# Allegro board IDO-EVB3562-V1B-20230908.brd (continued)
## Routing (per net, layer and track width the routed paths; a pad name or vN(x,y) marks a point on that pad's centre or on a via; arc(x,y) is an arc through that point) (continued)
RMII_MDIO: length 16.3
  TOP w0.127: v1(78.05,47.76) 78.05,49.22 78.75,49.92 78.75,55.51 80.68,57.44 80.68,58.07 81.79,59.19 M1.41
  BOTTOM w0.127: v1(78.05,47.76) 79.34,49.05 R202.1
RMII_RST_: length 4.4
  BOTTOM w0.127: U17.21 33.82,54.64 34.2,54.26 C340.2 R204.1 R208.2
RMII_RSTN: length 57.5
  TOP w0.127: M1.32 80.52,50.19 79.03,48.7 79.03,46.63 79.15,46.52 79.15,46.13 78.9,45.88 77.31,45.88 v1(76.28,46.91)
  BOTTOM w0.127: v1(76.28,46.91) 75.77,46.39 66.32,46.39 61.29,41.36 50.09,41.36 43.97,47.48 38.65,47.48 36.44,49.69 36.44,51.57 R208.1
RMII_RXD0: length 59.9
  TOP w0.127: M1.37 81.53,55.19 81.07,55.64 v1(80.57,55.64)
  BOTTOM w0.127: R197.2 43.49,59.13 43.49,50.68 50.96,43.21 60.42,43.21 65.68,48.47 74.57,48.47 75.81,49.71 76.47,49.71 76.78,50.02 76.78,51.39 77.54,52.16 77.54,54.18 79.1,55.73 80.48,55.73 v1(80.57,55.64)
RMII_RXD1: length 64.4
  TOP w0.127: v1(83.22,55.63) 83.06,55.48 83.06,52.71 82.54,52.19 M1.34
  BOTTOM w0.127: R196.2 42.04,59.6 43.24,58.4 43.24,50.57 50.85,42.96 60.53,42.96 65.78,48.21 74.67,48.21 75.92,49.46 76.58,49.46 77.03,49.91 77.03,51.28 77.8,52.05 77.8,54.07 79.2,55.47 80.07,55.47 80.37,55.18 80.76,55.18 81.22,55.63 v1(83.22,55.63)
RMII_RXER: length 67.9
  TOP w0.127: M1.33 81.16,51.19 78.78,48.81 78.78,46.62 v1(78.55,46.39)
  BOTTOM w0.127: v1(78.55,46.39) 78.07,45.91 77.22,45.91 76.61,45.3 66.82,45.3 61.76,40.24 49.62,40.24 43.47,46.39 38.2,46.39 36.04,48.55 33.18,48.55 29.75,51.98 28.99,51.98 27.97,52.99 27.97,54.84 R210.1
RMII_TXD0: length 6.1
  TOP w0.127: M1.40 81.91,58.19 79.64,55.91 v1(79.64,54.35)
  BOTTOM w0.127: R199.1 v1(79.64,54.35)
RMII_TXD0_: length 57.7
  BOTTOM w0.127: U17.16 37.88,54.15 37.88,49.36 38.99,48.24 44.28,48.24 50.41,42.12 60.98,42.12 66.05,47.2 75.09,47.2 76.34,48.44 77,48.44 78.05,49.49 78.05,50.86 78.65,51.46 78.65,52.81 R199.2
RMII_TXD1: length 6.6
  TOP w0.127: v1(81.06,53.37) 80.1,54.33 80.1,55.95 81.34,57.19 M1.39
  BOTTOM w0.127: R198.1 80.37,52.67 v1(81.06,53.37)
RMII_TXD1_: length 57
  BOTTOM w0.127: U17.17 35.82,54.48 37.26,53.05 37.26,49.59 38.86,47.99 44.18,47.99 50.3,41.86 61.08,41.86 66.16,46.94 75.2,46.94 76.44,48.19 77.1,48.19 78.3,49.39 78.3,50.76 78.9,51.36 78.9,52.05 R198.2
RMII_TXEN: length 8.3
  TOP w0.127: M1.38 83.32,56.19 83.68,55.83 83.68,55.18 v1(83.53,55.02)
  BOTTOM w0.127: R201.1 80.49,51.59 80.83,51.93 80.83,52.77 80.97,52.91 81.26,52.91 81.7,53.35 81.7,54.63 82,54.92 83.43,54.92 v1(83.53,55.02)
RMII_TXEN_: length 58
  BOTTOM w0.127: R201.2 79.47,51.57 78.55,50.65 78.55,49.28 77.21,47.94 76.55,47.94 75.3,46.69 66.26,46.69 61.19,41.61 50.2,41.61 44.07,47.74 38.75,47.74 36.69,49.79 36.69,53.08 36.56,53.22 35.19,53.22 34.48,53.93 34.48,54.49 34.32,54.65 U17.20
RN: length 2.3
  BOTTOM w0.102: R206.1 34.72,61.74 34.72,60.76 34.7,60.73 34.7,60.24 34.82,60.12 U17.6
RP: length 2.3
  BOTTOM w0.102: R206.2 34.47,61.74 34.47,60.86 34.44,60.84 34.44,60.22 34.32,60.1 U17.5
RS232_RX6: length 1.5
  TOP w0.127: U42.13 110.55,13.67 110.62,13.75 L42.1
RS232_RX6_: length 51.6
  TOP w0.127: v1(96.48,4.68) 96.1,4.3 93.66,4.3 J55.2 ; L42.2 112.89,13.75 113.01,13.62 117.89,13.62 120.86,10.65 123.93,10.65 v1(124.24,10.95)
  BOTTOM w0.127: v1(124.24,10.95) 125.02,10.17 125.02,8.8 122.52,6.3 120.49,6.3 120.28,6.51 118.55,6.51 118.06,6.03 99.34,6.03 98.39,5.08 96.88,5.08 v1(96.48,4.68)
RS232_RX8: length 3.7
  TOP w0.127: U42.8 102.91,11.07 102.31,11.67 101.48,11.67 101.14,11.34 L41.1
RS232_RX8_: length 25.3
  TOP w0.127: L41.2 98.96,11.34 98.2,10.57 95.2,10.57 91.46,6.83 91.46,2.04 90.77,1.35 83.51,1.35 J54.2
RS232_TX6: length 1.6
  TOP w0.127: L43.1 110.73,14.64 110.41,14.32 U42.14
RS232_TX6_: length 51.1
  TOP w0.127: v1(125,10.95) 124.54,11.42 123.92,11.42 123.4,10.9 120.99,10.9 118.02,13.88 113.19,13.88 112.43,14.64 L43.2 ; J55.3 95.32,3.97 96.66,3.97 v1(97.31,4.61)
  BOTTOM w0.127: v1(97.31,4.61) 98.29,4.61 99.45,5.77 118.17,5.77 118.65,6.26 120.17,6.26 120.38,6.04 122.63,6.04 125.38,8.8 125.38,10.57 v1(125,10.95)
RS232_TX8: length 1.8
  TOP w0.127: U42.7 103.03,11.72 102.58,12.17 L40.1
RS232_TX8_: length 25.1
  TOP w0.127: L40.2 101.04,11.89 99.15,11.89 98.09,10.83 95.1,10.83 91.21,6.94 91.21,2.14 90.66,1.6 85.26,1.6 J54.3
RSET0: length 4.8
  BOTTOM w0.203: U16.39 51.67,58.71 51.39,58.99 51.39,59.35 50.69,60.05 50.69,61.2 49.75,62.14 R183.2
RSET2: length 3
  BOTTOM w0.127: U15.31 71.4,59.45 70.98,59.88 70.72,59.88 69.86,60.74 R158.2
RXD0: length 5.2
  BOTTOM w0.127: U17.9 37.1,59.06 38.19,60.15 39.73,60.15 40.22,60.64 40.88,60.64 R197.1
RXD1: length 6.6
  BOTTOM w0.127: U17.10 37.66,58.56 R212.1 39.26,59.04 40.43,59.04 R196.1 R211.1
RXDV: length 3.3
  BOTTOM w0.127: R217.1 38.13,60.74 37.52,60.13 36.02,60.13 35.82,59.92 U17.8
RXER/FXEN: length 3.5
  BOTTOM w0.127: R210.2 R220.1 30.77,56.42 31.4,57.06 U17.28
RXN: length 25.2
  BOTTOM w0.102: R206.8 34.72,63.04 34.72,63.37 34.81,63.45 34.81,64.13 D80.4 34.81,64.56 34.81,65.69 35.52,66.4 35.52,67.62 33.05,70.09 33.05,71.65 28.82,75.88 25.26,75.88 24.57,75.19 24.57,74 22.61,72.04 J23.6
RXP: length 25.2
  BOTTOM w0.102: J23.3 26.12,74.53 26.12,73.79 25.31,72.98 24.59,72.98 24.42,73.16 24.42,73.49 24.82,73.89 24.82,75.09 25.36,75.62 28.72,75.62 32.8,71.54 32.8,69.98 35.26,67.52 35.26,67.29 D80.3 35.26,66.8 35.26,66.51 34.55,65.8 34.55,63.56 34.47,63.47 34.47,63.04 R206.7
SARADC0_BOOT: length 24.1
  TOP w0.127: v1(87.63,61.03) R1202.1 ; v1(79.92,43.97) 79.53,44.36 M1.179
  BOTTOM w0.127: v1(79.92,43.97) 79.92,44.36 82.71,47.15 82.71,49.72 86.14,53.14 86.14,57.06 86.65,57.56 87.41,57.56 88.88,59.04 88.88,59.77 v1(87.63,61.03)
SARADC0_IN1_KEY/RECOVERY: length 26.2
  TOP w0.203: M1.56 68.87,62.89 68.1,63.66 68.1,65.69 70.77,68.35 73.9,68.35 76.41,70.86 76.41,74.57 74.55,76.43 74.55,81.34 R264.1
SARADC1_IN0: length 99.2
  TOP w0.127: v1(64.02,66.71) 64.02,66.76 63.91,66.86 C272.2 63.51,66.87 63.51,63.61 62.87,62.97 M1.62 ; v1(74.04,25.35) 73.41,25.98 73.41,31.89 71.66,33.64 71.66,37.05 72.85,38.24 72.85,50.69 71.85,51.69 71.85,53.33 71.15,54.03 71.15,55.05 68.38,57.82 68.38,60.64 67.6,61.42 v1(66.43,61.42) ; v1(112.17,9.68) 112.17,9.18 111.92,8.92 R350.1
  BOTTOM w0.127: v1(74.04,25.35) 74.32,25.07 78.21,25.07 84.61,18.67 85.66,18.67 90.35,13.98 101.34,13.98 102.1,13.22 107.74,13.22 110.39,10.57 111.44,10.57 112.15,9.86 112.15,9.7 v1(112.17,9.68) ; v1(64.02,66.71) 64.09,66.63 64.14,66.63 64.19,66.58 64.38,66.58 65.9,65.07 66.5,64.46 66.5,61.48 v1(66.43,61.42)
SARADC1_IN1: length 102.9
  TOP w0.127: v1(73.26,25.38) 73.05,25.59 73.05,31.78 71.38,33.46 71.38,37.17 72.52,38.31 72.52,48.99 69.76,51.75 69.76,53.35 v1(68.98,54.13) ; v1(62.9,66.58) C273.2 62.47,66.85 62.47,63.54 61.87,62.94 M1.63 ; v1(111.45,9.68) 111.45,9.03 R349.1
  BOTTOM w0.127: v1(62.9,66.58) 63.49,65.99 64.25,65.99 66.12,64.13 66.12,62.09 65.84,61.81 65.84,60.32 64.49,58.97 64.49,54.6 65.28,53.81 68.66,53.81 v1(68.98,54.13) ; v1(73.26,25.38) 73.26,25.3 73.86,24.69 78.19,24.69 84.5,18.39 85.4,18.39 90.19,13.6 101.18,13.6 101.94,12.84 107.58,12.84 110.23,10.19 110.97,10.19 111.45,9.71 v1(111.45,9.68)
SARADC1_IN2: length 94.5
  TOP w0.127: v1(61.88,66.58) C274.2 61.46,66.85 61.46,63.52 60.87,62.93 M1.64 ; R348.1 v1(102.78,8.45) ; v1(71.66,23.03) 71.66,23.04 72.42,23.8 72.42,31.48 70.82,33.08 70.82,37.4 71.86,38.44 71.86,48.28 68.05,52.09 68.05,53.14 65.23,55.95 65.23,59.04 v1(63.84,60.43)
  BOTTOM w0.127: v1(61.88,66.58) 64.47,64 64.47,60.96 63.94,60.43 v1(63.84,60.43) ; v1(71.66,23.03) 71.66,23.04 71.71,23.09 72.36,23.09 72.55,22.89 76.11,22.89 77.1,21.9 78.44,21.9 84.05,16.3 84.18,16.3 86.68,13.79 86.68,12.3 88.14,10.84 90.08,10.84 90.36,11.12 97.24,11.12 98,10.35 100.69,10.35 102.6,8.45 v1(102.78,8.45)
SARADC1_IN3: length 94.5
  TOP w0.127: v1(63.8,61.13) 64.13,61.13 65.26,60 66.73,60 67.29,59.44 67.29,56.34 68.38,55.25 68.38,53.96 69.35,52.99 69.35,51.51 72.19,48.67 72.19,38.37 71.1,37.28 71.1,33.27 72.7,31.66 72.7,23.09 v1(72.11,22.49) ; v1(60.87,66.58) C275.2 60.44,66.85 60.44,66.03 60.36,65.95 60.36,64.1 59.87,63.6 M1.65 ; R347.1 v1(101.76,8.45)
  BOTTOM w0.127: v1(101.76,8.45) 101.76,8.57 100.36,9.97 97.84,9.97 97.03,10.78 90.57,10.78 90.23,10.45 88.02,10.45 86.3,12.17 86.3,13.77 86.2,13.87 86.2,13.88 84.06,16.02 83.93,16.02 78.32,21.62 76.98,21.62 76.09,22.51 72.13,22.51 v1(72.11,22.49) ; v1(63.8,61.13) 63.8,63.65 v1(60.87,66.58)
SARADC1_IN4: length 94.7
  TOP w0.127: R346.1 101.03,8.08 v1(101.03,8.45) ; v1(71.44,22.27) 71.12,22.59 71.12,23.26 72.14,24.28 72.14,31.29 70.54,32.89 70.54,37.51 70.54,37.52 70.54,37.52 71.53,38.51 71.53,48.15 67.72,51.96 67.72,53 64.9,55.81 64.9,58.53 63.2,60.23 63.2,60.73 v1(63.05,60.89) ; v1(59.98,66.6) 59.85,66.72 C276.2 59.47,66.89 59.47,66.2 59.95,65.72 59.95,64.32 58.87,63.24 M1.66
  BOTTOM w0.127: v1(59.98,66.6) 63.17,63.4 63.17,61.02 v1(63.05,60.89) ; v1(71.44,22.27) 71.74,21.98 76,21.98 76.23,21.98 76.87,21.34 78.21,21.34 83.81,15.74 83.94,15.74 85.92,13.76 85.92,11.99 87.82,10.09 90.46,10.09 90.82,10.45 96.82,10.45 97.81,9.47 100.15,9.47 101.03,8.59 v1(101.03,8.45)
SARADC1_IN5: length 96
  TOP w0.127: v1(100.32,8.45) 100.32,8.39 R345.1 ; v1(59,66.58) 58.83,66.75 C277.2 58.45,66.89 58.45,66.45 59.57,65.34 59.57,64.52 57.87,62.82 M1.67 ; v1(70.79,22.01) 70.79,23.4 71.86,24.47 71.86,31.1 70.41,32.56 70.26,32.71 70.26,37.72 71.2,38.66 71.2,48.01 67.39,51.82 67.39,52.86 64.57,55.68 64.57,58.38 62.65,60.3 v1(62.55,60.3)
  BOTTOM w0.127: v1(70.79,22.01) 71.1,21.7 76.11,21.7 76.59,21.23 76.75,21.06 78.09,21.06 83.7,15.46 83.76,15.46 83.81,15.4 85.41,13.8 85.41,11.86 87.59,9.68 90.66,9.68 91.1,10.12 96.61,10.12 97.78,8.96 99.94,8.96 100.32,8.57 v1(100.32,8.45) ; v1(59,66.58) 59.71,65.87 60.05,65.87 62.58,63.34 62.58,61.67 62.45,61.54 62.45,60.39 v1(62.55,60.3)
SD_CD: length 2.8
  TOP w0.127: R28.2 112.68,74.12 112.72,74.16 J6.9
SD_CLK: length 38.2
  TOP w0.127: v1(81.28,69.93) 81.02,69.93 80.82,69.72 79.86,69.72 78.65,68.51 C279.2 R25.2 ; J6.5 v1(108.32,77.38)
  BOTTOM w0.127: v1(81.28,69.93) 81.45,69.93 81.93,70.41 81.93,70.59 81.71,70.81 81.71,70.99 81.89,71.17 82.07,71.17 82.29,70.95 82.47,70.95 82.65,71.13 82.65,71.31 82.39,71.57 82.39,71.75 82.57,71.93 82.75,71.93 83.01,71.67 83.19,71.67 83.54,72.01 94.52,72.01 98.39,75.88 105.47,75.88 106.97,77.38 v1(108.32,77.38)
SDMMC0_CLK: length 7.3
  TOP w0.127: M1.51 73.87,63.33 75.22,64.68 76.61,64.68 77.63,65.69 R25.1
SDMMC0_CMD: length 47.5
  TOP w0.127: v1(80.41,70.31) 79.79,70.31 78.34,68.87 76.56,68.87 74.87,67.17 71.26,67.17 70.23,66.15 70.23,65.24 71.9,63.56 72.58,63.56 72.87,63.26 M1.52 ; J6.3 v1(106.12,77.38)
  BOTTOM w0.127: v1(106.12,77.38) 105,76.26 98.23,76.26 94.49,72.52 82.61,72.52 v1(80.41,70.31)
SDMMC0_D0: length 47.1
  TOP w0.127: v1(80.28,68.45) 79.62,68.45 79.43,68.26 79.43,67.77 79.76,67.44 79.76,66.6 79.18,66.02 79.01,66.02 78.65,66.38 78.47,66.38 78.29,66.2 78.29,66.02 78.65,65.66 78.65,65.48 78.48,65.31 77.97,65.31 76.82,64.17 75.6,64.17 74.87,63.44 M1.50 ; J6.7 v1(110.52,77.38)
  BOTTOM w0.127: v1(80.28,68.45) 80.64,68.8 81.31,68.8 81.85,69.35 81.85,69.79 83.57,71.5 94.55,71.5 98.42,75.37 105.68,75.37 107.06,76.75 109.89,76.75 v1(110.52,77.38)
SDMMC0_D1: length 47.8
  TOP w0.127: M1.49 75.87,63.42 76.36,63.91 76.93,63.91 78.07,65.06 78.7,65.06 78.98,65.34 79.25,65.34 79.65,64.94 79.85,64.94 80.03,65.12 80.03,65.28 79.56,65.74 79.56,65.92 79.74,66.1 79.92,66.1 80.31,65.71 80.52,65.71 80.7,65.89 80.7,66.04 80.28,66.46 80.28,66.64 v1(80.28,67.74) ; J6.8 111.62,76.95 v1(111.2,77.38)
  BOTTOM w0.127: v1(80.28,67.74) 80.28,67.79 80.92,68.43 81.29,68.43 82.1,69.24 82.1,69.68 83.67,71.25 94.66,71.25 98.52,75.11 105.78,75.11 107.16,76.49 110.31,76.49 v1(111.2,77.38)
SDMMC0_D2: length 47
  TOP w0.127: M1.54 70.87,63.87 69.72,65.03 69.72,66.36 71.04,67.68 74.4,67.68 76.33,69.62 77.9,69.62 79.41,71.13 v1(79.41,71.25) ; J6.1 v1(103.92,77.38)
  BOTTOM w0.127: v1(103.92,77.38) 103.45,77.85 103.28,77.85 103.16,77.72 103.16,77.02 103.03,76.89 102.78,76.89 102.65,77.02 102.65,77.72 102.52,77.85 101.01,77.85 99.93,76.76 97.98,76.76 94.24,73.03 82.32,73.03 80.55,71.25 v1(79.41,71.25)
SDMMC0_D3: length 48.5
  TOP w0.127: M1.53 71.87,63.23 69.97,65.13 69.97,66.25 71.15,67.43 74.5,67.43 76.4,69.32 78.44,69.32 v1(79.89,70.78) ; J6.2 v1(105.02,77.38)
  BOTTOM w0.127: v1(105.02,77.38) 104.15,76.51 102.35,76.51 102.23,76.64 102.23,77.22 102.1,77.35 101.85,77.35 101.72,77.22 101.72,76.64 101.59,76.51 101.34,76.51 101.21,76.64 101.21,77.07 101.08,77.2 100.83,77.2 100.7,77.07 100.7,76.64 100.58,76.51 98.1,76.51 94.37,72.77 82.43,72.77 80.43,70.78 v1(79.89,70.78)
SDMMC0_DET_L: length 88.6
  TOP w0.127: M1.171 79.87,18.56 79.27,19.16 77.53,19.16 77.16,19.52 76.88,19.52 76.81,19.59 76.11,19.59 75.09,20.61 75.09,21.75 76.89,23.55 79.43,23.55 79.92,24.04 79.92,25.69 80.98,26.75 80.98,32.98 81.21,33.21 81.21,49.03 v1(81.06,49.18) ; v1(87.82,58.81) 87.64,58.99 87.64,59.62 89.39,61.37 93.25,61.37 93.76,61.88 94.9,61.88 96.04,63.02 111.13,63.02 112.17,64.07 112.17,69.88 112.68,70.39 R28.1 R431.2
  BOTTOM w0.127: v1(87.82,58.81) 86.57,58.81 85.38,57.61 85.38,53.75 83.98,52.36 83.57,52.36 81.06,49.84 v1(81.06,49.18)
SDMMC1_CLK: length 84.4
  TOP w0.127: v1(74.45,35.95) 74.45,36.98 74.88,37.4 74.88,48.75 77.54,51.42 77.54,52.82 77.38,52.99 77.38,59.56 78.41,60.59 79.1,60.59 79.37,60.87 81.19,60.87 81.51,61.19 M1.43 ; R227.1 v1(119.58,31.98)
  BOTTOM w0.127: v1(119.58,31.98) 117.98,31.98 116.63,30.62 114.85,30.62 111.6,27.37 109.84,27.37 107.05,24.58 95.1,24.58 94.63,25.05 94.03,25.05 85.46,33.62 84.91,33.62 83.61,34.92 82.12,36.41 75.63,36.41 75.16,35.93 74.47,35.93 v1(74.45,35.95)
SDMMC1_CMD: length 87.3
  TOP w0.127: U18.16 v1(118.79,30.13) ; v1(74.12,34.64) 73.86,34.89 73.86,36.92 74.5,37.56 74.5,49.09 76.61,51.21 76.61,59.52 78.2,61.1 78.89,61.1 79.16,61.37 80.53,61.37 80.87,61.72 M1.44
  BOTTOM w0.127: v1(118.79,30.13) 118.45,29.79 118.45,29.61 118.81,29.25 118.81,29.07 118.63,28.89 118.45,28.89 118.09,29.25 117.91,29.25 117.73,29.07 117.73,28.89 118.14,28.48 118.14,28.3 117.96,28.12 116.78,28.12 116.7,28.05 113.71,28.05 109.23,23.56 93.99,23.56 84.94,32.61 84.67,32.61 82.75,34.52 74.23,34.52 v1(74.12,34.64)
SDMMC1_D0: length 86.5
  TOP w0.127: v1(72.76,35.39) 72.29,35.86 72.29,36.79 73.48,37.98 73.48,49.51 75.6,51.63 75.6,59.94 76.87,61.21 M1.48 ; U18.18 v1(116.99,30.03)
  BOTTOM w0.127: v1(72.76,35.39) 73.04,35.1 74.4,35.1 74.73,34.78 82.86,34.78 84.77,32.86 85.09,32.86 94.14,23.82 109.12,23.82 113.61,28.3 116.6,28.3 116.73,28.43 116.73,28.68 116.6,28.81 114.62,28.81 114.49,28.94 114.49,29.19 114.62,29.32 116.28,29.32 v1(116.99,30.03)
SDMMC1_D1: length 87.5
  TOP w0.127: U18.19 v1(116.09,30.03) ; M1.47 77.87,61.85 75.85,59.83 75.85,51.52 73.74,49.41 73.74,37.87 72.91,37.05 72.91,36.29 v1(72.76,36.14)
  BOTTOM w0.127: v1(116.09,30.03) 115.7,29.64 114.59,29.64 111.16,26.22 110.98,26.22 110.46,26.74 110.28,26.74 110.1,26.56 110.1,26.38 110.62,25.86 110.62,25.68 110.44,25.5 110.26,25.5 109.67,26.09 109.48,26.09 109.31,25.92 109.31,25.74 109.91,25.14 109.91,24.96 109.73,24.78 109.55,24.78 108.9,25.43 108.72,25.43 108.54,25.25 108.54,25.07 109.19,24.42 109.19,24.24 109.02,24.07 94.29,24.07 85.25,33.12 84.88,33.12 82.96,35.03 82.67,35.03 82.54,35.16 82.54,35.45 82.41,35.58 82.16,35.58 82.03,35.45 82.03,35.16 81.9,35.03 75.91,35.03 75.79,35.16 75.79,35.47 75.66,35.59 75.4,35.59 75.28,35.47 75.28,35.16 75.15,35.03 74.83,35.03 74.51,35.36 73.54,35.36 v1(72.76,36.14)
SDMMC1_D2: length 87.7
  TOP w0.127: v1(72.83,34.21) 73.01,34.38 73.01,34.99 73.22,35.2 73.22,37 73.99,37.77 73.99,49.3 76.11,51.42 76.11,59.73 77.99,61.61 78.68,61.61 78.87,61.8 M1.46 ; v1(120.4,30.11) 120.59,29.92 U18.14
  BOTTOM w0.127: v1(120.4,30.11) 120.4,29.54 118.41,27.54 113.92,27.54 109.44,23.06 93.78,23.06 84.73,32.1 84.46,32.1 82.64,33.92 73.12,33.92 v1(72.83,34.21)
SDMMC1_D3: length 86.7
  TOP w0.127: U18.15 v1(119.69,30.13) ; v1(73.48,34.42) 73.48,36.89 74.24,37.66 74.24,49.2 76.36,51.31 76.36,59.62 78.09,61.35 78.78,61.35 79.06,61.63 79.66,61.63 79.87,61.84 M1.45
  BOTTOM w0.127: v1(119.69,30.13) 119.69,29.18 118.3,27.79 113.82,27.79 109.33,23.31 93.88,23.31 84.84,32.35 84.56,32.35 82.74,34.17 73.72,34.17 v1(73.48,34.42)
SENSER_SCL: length 1.3
  TOP w0.127: R343.2 67.46,10.38 U20.6
SENSER_SDA: length 1.2
  TOP w0.127: U20.5 67.7,9.73 R344.2
SIM_CLK: length 15.3
  TOP w0.127: v1(113.7,55.58) 113.7,54.13 114.45,53.39 116.19,53.39 R55.2
  BOTTOM w0.127: J11.C3 112.68,60.07 C62.2 112.55,58.67 112.55,56.72 v1(113.7,55.58) 114.16,56.04 115.6,56.04 116.24,55.4 U8.6
SIM_DATA: length 47.9
  TOP w0.127: v1(112.68,83.22) 112.68,80.49 115.08,78.09 115.08,75.09 113.67,73.68 113.67,65.28 v1(114.9,64.04) ; v1(118.85,53.04) 118.84,53.06 R53.1 118.78,53.94 R54.2
  BOTTOM w0.127: 123.76,55.4 123.98,55.18 123.98,53.91 123.69,53.61 119.43,53.61 v1(118.85,53.04) ; 123.76,55.4 124.37,56.01 124.37,58.27 C63.2 122.66,59.98 118.97,59.98 v1(114.9,64.04) ; 123.76,55.4 U8.3 ; J11.C7 v1(112.68,83.22)
SIM_RST: length 17.7
  TOP w0.127: R56.2 R440.1 114.25,54.41 114.25,55.78 v1(113.74,56.29)
  BOTTOM w0.127: J11.C2 110.14,61.7 111.16,62.72 113.49,62.72 113.74,62.47 113.74,59.83 C61.2 113.74,58.73 v1(113.74,56.29) 114.13,56.67 U8.7
SNSN: length 2.4
  TOP w0.254: M1.178 78.29,40.82 v1(78.29,41.77)
  BOTTOM w0.254: v1(78.29,41.77) 77.76,42.3 TP1.1
SNSP: length 2.3
  TOP w0.254: M1.177 78.56,35.66 v1(78.43,35.53)
  BOTTOM w0.254: v1(78.43,35.53) 77.69,35.53 TP2.1
SPI0_CLK_M0: length 66.8
  TOP w0.127: v1(68.75,25.85) 67.88,24.97 67.88,20.45 68.87,19.46 M1.160 ; R363.2 116.87,8.94 117.08,9.16 117.08,10.31 v1(116.57,10.83)
  BOTTOM w0.127: v1(68.75,25.85) 68.97,26.07 69.76,26.07 70.4,26.71 71.5,26.71 72.31,27.52 78.51,27.52 83.11,22.91 83.93,22.91 86.27,20.57 86.71,20.57 91.33,15.95 102.07,15.95 102.89,15.13 109.31,15.13 111.84,12.6 114.5,12.6 116.27,10.83 v1(116.57,10.83)
SPI0_CLK_M0/PWM0_M0: length 7
  TOP w0.127: J44.4 118.85,3.39 118.85,4.86 116.87,6.84 R363.7
SPI0_CSN0_M0: length 68.4
  TOP w0.127: M1.159 67.87,18.72 68.23,19.08 68.23,19.46 67.6,20.1 67.6,23.65 67.6,25.43 68.82,26.65 v1(69.68,26.65) ; v1(117.43,10.81) 117.43,10.48 117.47,10.44 117.47,9.02 117.42,8.98 R363.1
  BOTTOM w0.127: v1(117.43,10.81) 116.76,11.47 116.76,11.83 116.25,12.34 115.29,12.34 114.66,12.98 112,12.98 109.47,15.51 103.05,15.51 102.23,16.33 91.49,16.33 86.87,20.95 86.43,20.95 84.04,23.34 83.22,23.34 78.67,27.9 72.15,27.9 71.34,27.09 70.12,27.09 v1(69.68,26.65)
SPI0_CSN0_M0/PWM5_M0: length 8.8
  TOP w0.127: J44.2 121.67,3.11 120.05,3.11 119.11,4.05 119.11,4.96 117.42,6.65 R363.8
SPI0_MISO_M0: length 64.6
  TOP w0.127: R363.4 v1(115.82,9.92) ; v1(68.87,24.77) 68.42,24.32 68.42,20.84 70.87,18.39 M1.162
  BOTTOM w0.127: v1(115.82,9.92) 115.64,10.1 115.64,10.56 114.24,11.96 111.58,11.96 109.05,14.49 102.63,14.49 101.8,15.32 91.06,15.32 86.44,19.94 85.95,19.94 83.61,22.28 82.85,22.28 78.25,26.88 72.57,26.88 71.76,26.07 70.65,26.07 69.66,25.09 69.18,25.09 v1(68.87,24.77)
SPI0_MISO_M0/PWM2_M0: length 6.2
  TOP w0.127: R363.5 115.82,5.84 116.26,5.39 116.26,2.98 J44.8
SPI0_MOSI_M0: length 65.5
  TOP w0.127: v1(69.43,25.56) 69.13,25.26 68.7,25.26 68.17,24.73 68.17,20.67 69.87,18.97 M1.161 ; v1(116.49,10.07) 116.37,9.94 R363.3
  BOTTOM w0.127: v1(116.49,10.07) 114.34,12.22 111.68,12.22 109.15,14.75 102.73,14.75 101.91,15.57 91.17,15.57 86.55,20.19 86.06,20.19 83.72,22.53 82.96,22.53 78.35,27.14 72.47,27.14 71.66,26.33 70.52,26.33 69.76,25.56 v1(69.43,25.56)
SPI0_MOSI_M0/PWM1_M0: length 6.2
  TOP w0.127: R363.6 116.37,5.77 116.59,5.54 116.59,3.11 J44.6
SPK_CTL_L: length 13.3
  TOP w0.127: U25.12 U25.5 98.99,16.42 99.32,16.75 101.4,16.75 102.75,18.09 102.75,18.32 102.62,18.45 Q5.3
SPK_EN_H_GPIO4_B6_D: length 96.7
  TOP w0.127: v1(35.68,32.98) 35.68,33.39 36.47,34.19 37.57,34.19 ; v1(95.71,9.25) 95.71,9.63 96.15,10.07 98.41,10.07 98.92,10.58 104.56,10.58 105.86,11.88 105.86,17.21 106.38,17.74 106.38,18.57 R454.1 R1201.1
  BOTTOM w0.127: v1(95.71,9.25) 95.71,9.26 93.79,9.26 93.58,9.26 93.12,8.8 87.5,8.8 84.9,11.4 84.9,13.59 83.6,14.89 83.52,14.89 77.85,20.56 75.93,20.56 75.47,20.1 75.47,19.74 74.96,19.24 70.85,19.24 68.46,21.62 65.68,21.62 63.62,23.69 43.79,23.69 41.48,25.99 41.48,27.91 36.55,32.84 35.81,32.84 v1(35.68,32.98)
SPKN_OUT: length 13.4
  TOP w0.508: v1(72.8,20.35) 72.8,21.78 75.72,24.7 75.72,26.45 76.99,27.72 78.26,27.72 78.56,28.02 M1.175
  BOTTOM w0.508: TP5.1 v1(72.8,20.35)
SPKP_OUT: length 11.3
  TOP w0.508: v1(73.82,20.35) 73.82,21.64 76.74,24.57 76.74,26.07 77.5,26.83 78.16,26.83 78.56,26.43 M1.174
  BOTTOM w0.508: v1(73.82,20.35) 73.94,20.23 TP4.1
SYS_LED_H: length 3.5
  TOP w0.254: R1173.1 75.72,84.43 R21.1 R415.2
TN: length 2.3
  BOTTOM w0.102: U17.4 33.82,60.1 33.7,60.22 33.7,60.54 33.67,60.57 33.67,61.74 R206.3
TP: length 2.3
  BOTTOM w0.102: U17.3 33.32,60.09 33.44,60.21 33.44,60.44 33.42,60.46 33.42,61.74 R206.4
TP_INT: length 22.1
  TOP w0.127: J13.3 7.5,44.11 8.52,45.12 v1(10.07,45.12) ; R449.1 11.79,31.15 v1(11.84,31.15) 11.84,31.43 12.3,31.89 U59.4
  BOTTOM w0.127: v1(10.07,45.12) 9.6,44.65 9.6,44.05 10.24,43.4 10.24,39.85 12.78,37.32 12.78,32.08 v1(11.84,31.15)
TP_INT_L_GPIO0_B6_D: length 63
  TOP w0.127: U59.8 15.04,31.89 15.53,31.4 v1(15.53,29.72) ; M1.156 64.87,18.63 v1(64.55,18.96)
  BOTTOM w0.127: v1(64.55,18.96) 64.44,19.06 64.44,21.07 63.09,22.42 43.26,22.42 40.21,25.46 40.21,27.38 36.1,31.5 31.74,31.5 29.18,28.94 24.89,28.94 23.61,30.22 18.52,30.22 17.3,29 16.25,29 v1(15.53,29.72)
TP_RST: length 21.4
  TOP w0.127: J13.2 7.68,43.61 8.69,44.62 9.8,44.62 v1(10.07,44.36) ; U59.5 12.44,31.49 12.31,31.36 12.31,30.85 v1(11.84,30.39)
  BOTTOM w0.127: v1(10.07,44.36) 10.5,43.92 10.5,39.96 13.03,37.43 13.03,31.57 v1(11.84,30.39)
TP_RST_L_GPIO0_B5_D: length 62.6
  TOP w0.127: v1(14.85,29.72) 15.15,30.01 15.15,31.27 14.93,31.49 U59.7 ; M1.155 v1(63.87,18.99)
  BOTTOM w0.127: v1(63.87,18.99) 63.87,19.51 64.16,19.81 64.16,20.99 62.99,22.16 43.15,22.16 39.96,25.36 39.96,27.28 36.76,30.47 35.11,30.47 34.61,30.97 31.57,30.97 29.29,28.69 24.78,28.69 23.51,29.96 18.62,29.96 17.41,28.74 15.82,28.74 v1(14.85,29.72)
TP_SCL: length 21.7
  TOP w0.127: v1(10.07,45.88) 9.81,45.62 8.41,45.62 7.4,44.61 J13.4 ; R422.1 11.68,32.06 v1(11.81,32.06) 12.04,32.29 U59.3
  BOTTOM w0.127: v1(11.81,32.06) 11.85,32.06 12.52,32.73 12.52,37.22 9.99,39.75 9.99,43.3 9.35,43.94 9.35,45.16 v1(10.07,45.88)
TP_SDA: length 21.7
  TOP w0.127: R421.1 11.68,32.54 v1(11.87,32.74) 12.16,32.74 12.21,32.69 U59.2 ; J13.5 7.27,45.11 8.29,46.12 9.55,46.12 v1(10.07,46.64)
  BOTTOM w0.127: v1(11.87,32.74) 12.27,33.14 12.27,37.11 9.74,39.64 9.74,43.19 9.09,43.84 9.09,45.67 v1(10.07,46.64)
TXN: length 19.5
  BOTTOM w0.102: J23.2 27.52,71.95 27.78,72.04 28.12,72.71 27.96,73.18 27.7,73.31 27.05,73.31 26.35,72.6 26.35,71.61 26.88,71.08 30.34,71.08 33.59,67.83 33.59,66.1 32.9,65.41 32.9,64.57 D80.6 32.9,64.12 32.9,63.77 33.05,63.61 33.42,63.61 33.67,63.36 33.67,63.04 R206.6
TXP: length 19.5
  BOTTOM w0.102: R206.5 33.42,63.04 33.42,63.25 33.32,63.36 32.95,63.36 32.64,63.66 32.64,65.51 33.33,66.2 33.33,66.83 D80.1 33.33,67.26 33.33,67.72 30.23,70.82 26.78,70.82 26.09,71.5 26.09,72.71 26.95,73.56 27.76,73.56 27.94,73.47 28.08,73.52 J23.1
UART0_RX_M0_DEBUG: length 94.1
  TOP w0.127: M1.165 73.87,17 v1(73.95,16.92) ; v1(127.79,40.93) 127.79,41.1 127.21,41.69 R261.1 R463.1 ; v1(88.69,11.67) 88.49,11.46 76.11,11.46 v1(75.6,11.97)
  BOTTOM w0.127: v1(73.95,16.92) 73.95,15.53 75.6,13.88 v1(75.6,11.97) ; v1(127.79,40.93) 127.79,40.42 126.78,39.4 126.78,27.85 127.16,27.46 127.16,24.54 126.4,23.78 122.97,23.78 119.29,20.1 119.29,16.03 118.02,14.76 118.02,13.37 119.88,11.51 119.88,9.96 119.07,9.15 117.55,9.15 116.67,8.27 104.62,8.27 102.72,10.17 102.12,10.17 101.06,11.23 98.36,11.23 97.6,11.99 89.62,11.99 89.55,12.06 89.09,12.06 v1(88.69,11.67)
UART0_TX_M0_DEBUG: length 101.2
  TOP w0.127: v1(74.84,16.92) 74.87,16.96 M1.166 ; v1(130.59,42.07) 128.35,42.07 127.21,43.21 126.45,43.21 R464.1 ; v1(75.6,11.21) 75.72,11.08 88.89,11.08 v1(89.36,11.56)
  BOTTOM w0.127: v1(74.84,16.92) 74.33,16.42 74.33,15.65 76.11,13.88 76.11,11.72 v1(75.6,11.21) ; v1(130.59,42.07) 129.95,42.07 127.03,39.15 127.03,27.97 127.41,27.59 127.41,24.42 126.52,23.53 123.1,23.53 119.54,19.97 119.54,15.91 118.27,14.64 118.27,13.5 120.17,11.59 120.17,9.79 119.26,8.87 117.68,8.87 116.81,8 104.43,8 102.62,9.81 102.01,9.81 100.92,10.9 98.22,10.9 97.46,11.66 89.46,11.66 v1(89.36,11.56)
UART3_CTSN_M1: length 137.9
  TOP w0.127: v1(64.63,64.75) 64.63,66.1 65.02,66.49 65.02,68.04 63.59,69.46 59.08,69.46 58.11,68.49 58.11,66.65 56.95,65.5 55.4,65.5 54.36,66.53 54.36,68.82 54.01,69.17 v1(52.92,69.17) ; v1(117.38,16.54) 119.41,16.54 119.69,16.82 U18.41 ; v1(68.9,29.57) 68.9,30.3 68.17,31.03 68.17,34.25 68.71,34.79 68.71,38.76 68.99,39.05 68.99,48.27 65.21,52.06 65.21,53.1 62.89,55.42 62.49,55.82 v1(62.49,57.13) ; v1(47.81,70.95) 46.75,69.88 45.47,69.88 42.04,66.46 42.04,63.81 42.87,62.99 M1.82
  BOTTOM w0.127: v1(52.92,69.17) 52.92,69.31 51.27,70.95 47.82,70.95 v1(47.81,70.95) ; v1(68.9,29.57) 69.18,29.29 70.49,29.29 71.13,29.93 79.24,29.93 83.99,25.18 84.77,25.18 86.88,23.08 87.62,23.08 92.33,18.36 102.71,18.36 103.08,18 110.31,18 110.47,18.15 115.34,18.15 R239.2 116.62,17.3 v1(117.38,16.54) ; v1(64.63,64.75) 64.95,64.75 65.73,63.97 65.73,62.24 65.46,61.97 65.46,60.48 62.49,57.51 v1(62.49,57.13)
UART3_RTSN_M1: length 176.1
  TOP w0.127: v1(125.26,40.41) 124.87,40.03 124.87,39.18 126.05,38.01 v1(126.27,38.01) ; v1(75.73,74.19) 75.22,73.68 75.22,71.25 73.58,69.62 70.39,69.62 68.44,67.66 67.4,67.66 v1(66.45,68.61) ; v1(117.51,15.02) 119.05,15.02 120.62,16.59 121.94,16.59 122.39,17.03 U18.44 ; M1.79 45.87,63.85 45.4,64.32 45.4,67.87 48.28,70.75 48.28,71.45 48.14,71.58 48.14,72.55 48.72,73.13 49.54,73.13 50.2,72.47 50.2,72.22 50.73,71.69 52.44,71.69 52.76,72.02 v1(54.53,72.02)
  BOTTOM w0.127: v1(126.27,38.01) 126.27,37.54 126.14,37.41 126.14,25.56 126.52,25.18 126.52,24.29 126.27,24.04 122.84,24.04 119.03,20.23 119.03,16.54 v1(117.51,15.02) ; v1(54.53,72.02) 54.76,72.02 56.32,70.45 60.93,70.45 61.86,69.53 63.25,69.53 64.17,68.61 v1(66.45,68.61) ; v1(75.73,74.19) 76.8,73.13 79.53,73.13 81.13,74.72 91.46,74.72 91.8,75.06 92.44,75.06 92.82,74.68 94.23,74.68 97.27,77.72 99.7,77.72 100.84,78.86 112.37,78.86 112.71,78.52 112.71,77.02 113.01,76.72 115.65,76.72 117.43,74.94 121.14,74.94 130.16,65.92 130.16,46.21 126.4,42.45 126.4,41.82 125.92,41.34 125.92,41.07 v1(125.26,40.41)
UART3_RX_M1: length 126.8
  TOP w0.127: M1.80 44.87,62.14 43.76,61.04 43.76,59.93 47.24,56.45 49.13,56.45 49.89,55.69 57.6,55.69 57.81,55.69 59.69,53.8 60.21,53.8 62.35,51.67 62.35,51.05 62.35,50.23 63.41,49.17 63.41,47.92 65.1,46.23 65.1,42.67 65.9,41.86 65.9,40.77 66.33,40.34 66.33,30.12 66.88,29.57 66.88,27.77 65.44,26.33 65.44,23.81 65.06,23.43 v1(64.73,23.43) ; v1(110.82,17.4) 109.94,17.4 108.62,16.09 108.62,10.75 108.54,10.67 v1(108.54,10.47) ; U18.42 120.59,17.34 119.16,15.91 117.3,15.91 v1(116.69,16.52)
  BOTTOM w0.127: v1(110.82,17.4) 111.08,17.15 113.54,17.15 114.89,15.81 115.98,15.81 v1(116.69,16.52) ; v1(108.54,10.47) 104.56,10.47 102.98,12.05 101.66,12.05 100.87,12.84 89.87,12.84 85.19,17.52 84.26,17.52 77.86,23.93 72.95,23.93 72.62,24.26 71.15,24.26 70.53,23.64 69.97,23.64 69.32,22.99 65.16,22.99 v1(64.73,23.43)
UART3_TX_M1: length 126
  TOP w0.127: M1.81 43.87,61.68 43.5,61.31 43.5,59.82 47.12,56.2 49.02,56.2 49.78,55.44 57.7,55.44 59.61,53.53 60.13,53.53 62.09,51.57 62.09,51.15 62.09,50.33 62.09,50.12 63.15,49.06 63.15,47.82 64.85,46.12 64.85,42.56 65.65,41.76 65.65,40.63 66.07,40.2 66.07,30 66.62,29.45 66.62,27.87 65.18,26.43 65.18,24.32 v1(64.97,24.11) ; U18.43 121.49,17.02 121.31,16.84 120.45,16.84 119.14,15.53 116.99,15.53 v1(116.01,16.5) ; v1(104.96,11.72) 105.52,12.28 105.52,17.33 v1(105.34,17.51)
  BOTTOM w0.127: v1(105.34,17.51) 110.22,17.51 110.6,17.89 111.31,17.89 111.75,17.45 113.61,17.45 114.99,16.06 115.57,16.06 v1(116.01,16.5) ; v1(104.96,11.72) 104.38,12.3 101.77,12.3 100.97,13.09 89.98,13.09 85.29,17.78 84.37,17.78 77.96,24.18 73.05,24.18 72.72,24.52 71.05,24.52 70.43,23.9 69.87,23.9 69.24,23.27 65.81,23.27 v1(64.97,24.11)
UART4_RX: length 4.2
  TOP w0.127: v1(119.2,5.53) 118.65,6.08 R369.2
  BOTTOM w0.127: v1(119.2,5.53) 118.15,4.48 J44.5
UART4_RX_M0: length 121.2
  TOP w0.127: R369.1 118.65,9.81 v1(118.02,10.45) ; v1(62.19,24.26) 62.19,24.64 63.33,25.79 63.33,27.29 63.74,27.69 63.74,38.92 63.19,39.46 63.19,40.5 62.41,41.29 62.41,45.02 60.76,46.67 60.76,48.22 59.25,49.73 58.97,49.73 57.92,50.77 57.92,51.56 56.44,53.03 44.27,53.03 44.23,53.08 41.43,53.08 38.32,56.19 37.57,56.19
  BOTTOM w0.127: v1(62.19,24.26) 62.36,24.09 64.14,24.09 67.8,27.74 69.75,27.74 69.9,27.6 71.03,27.6 71.84,28.41 78.88,28.41 83.43,23.85 84.27,23.85 86.58,21.55 86.99,21.55 91.7,16.84 102.44,16.84 103.26,16.02 109.68,16.02 110.09,15.61 110.66,15.61 110.87,15.82 111.26,15.82 111.53,15.55 111.53,15.41 113.45,13.49 114.87,13.49 115.51,12.85 116.7,12.85 118.02,11.53 v1(118.02,10.45)
UART4_TX: length 3.4
  TOP w0.127: R368.2 119.67,5.11 J44.3
UART4_TX_M0: length 121.2
  TOP w0.127: v1(62.87,24.65) 62.87,24.97 63.58,25.68 63.58,27.16 63.99,27.57 63.99,39.05 63.46,39.58 63.46,40.62 62.66,41.42 62.66,45.13 61.02,46.77 61.02,48.32 59.36,49.98 59.07,49.98 58.2,50.85 58.2,51.63 56.55,53.29 44.38,53.29 44.33,53.33 41.53,53.33 38.13,56.73 38.13,57.06 38,57.19 37.57,57.19 ; v1(118.52,10.95) 119.67,9.81 R368.1
  BOTTOM w0.127: v1(118.52,10.95) 118.52,11.39 116.81,13.1 115.61,13.1 114.97,13.74 113.58,13.74 111.78,15.54 111.78,15.66 111.35,16.09 110.07,16.09 109.89,16.27 103.36,16.27 102.54,17.09 91.8,17.09 87.09,21.81 86.68,21.81 84.37,24.11 83.62,24.11 79.07,28.66 71.65,28.66 70.84,27.85 70,27.85 69.86,28 67.69,28 64.34,24.65 v1(62.87,24.65)
UART6_RX: length 10
  TOP w0.127: R1167.1 112.55,12.73 113.32,11.97 113.32,10.57 113.57,10.32 113.57,9.56 112.94,8.92 112.94,8.09 R371.2 113.44,5.24 J44.9
UART6_RX_: length 1.6
  TOP w0.127: U42.12 110.39,13.02 110.68,12.73 R1167.2
UART6_RX_M0: length 65
  TOP w0.127: M1.164 72.87,18.25 71.05,20.07 69.95,20.07 68.99,21.03 68.99,23.68 v1(69.14,23.83) ; R371.1 113.83,8.87 v1(113.83,10.83) 113.83,12.17 R1208.1
  BOTTOM w0.127: v1(69.14,23.83) 69.28,23.83 69.6,24.15 70.32,24.15 70.94,24.77 71.54,24.77 72.87,26.1 77.95,26.1 84.88,19.17 85.87,19.17 90.54,14.5 101.54,14.5 102.31,13.73 107.95,13.73 110.56,11.12 113.53,11.12 v1(113.83,10.83)
UART6_TX: length 13.4
  TOP w0.127: J44.7 114.59,5.11 114.59,7.46 R370.2 114.93,8.05 114.93,9.55 v1(114.72,9.76) ; U42.11 110.48,12.37 110.7,12.15 112.43,12.15 113.06,11.51 113.06,9.81 v1(112.94,9.68)
  BOTTOM w0.127: v1(112.94,9.68) 113.4,9.68 113.48,9.76 v1(114.72,9.76)
UART6_TX_M0: length 65.6
  TOP w0.127: R370.1 114.08,8.86 114.08,10.07 v1(114.46,10.45) 114.46,11.91 R1207.1 ; M1.163 71.87,18.87 70.92,19.82 70.06,19.82 69.85,19.82 68.68,20.99 68.68,24.02 68.95,24.29 69.2,24.29 v1(69.53,24.62)
  BOTTOM w0.127: v1(69.53,24.62) 70.43,24.62 70.84,25.03 71.43,25.03 72.77,26.36 78.05,26.36 84.98,19.43 85.98,19.43 90.65,14.76 101.64,14.76 102.42,13.99 108.05,13.99 110.66,11.38 114.04,11.38 114.46,10.95 v1(114.46,10.45)
UART8_RX: length 9.8
  TOP w0.127: J44.13 109,5.87 109,7.15 108.74,7.4 R365.7 108.74,8.16 109.06,8.47 109.86,8.47 110.06,8.67 110.06,10.21 110.37,10.52 111.3,10.52 R1166.1
UART8_RX_: length 1.5
  TOP w0.127: R1166.2 110.7,11.21 110.56,11.07 U42.9
UART8_RX_M0: length 129.7
  TOP w0.127: v1(65.31,28.1) 65.78,28.57 65.78,29.08 65.27,29.59 65.27,39.78 64.74,40.31 64.74,41.19 63.93,41.99 63.93,45.66 62.29,47.3 62.29,48.85 60.61,50.53 60.61,51.32 57.33,54.6 49.24,54.6 48.6,55.24 42.5,55.24 40.59,57.14 39.99,57.14 39.48,57.65 39.48,61.42 39.87,61.82 M1.85 ; R365.2 108.74,9.79 v1(109.17,10.22)
  BOTTOM w0.127: v1(109.17,10.22) 109.37,10.22 110.54,9.05 116.34,9.05 117.22,9.93 118.71,9.93 119.08,10.29 119.08,11.19 117.33,12.94 116.91,13.36 115.87,13.36 113.92,15.31 113.92,15.75 113.03,16.63 110.43,16.63 110.29,16.78 103.57,16.78 102.5,17.86 92.12,17.86 87.41,22.57 86.66,22.57 84.56,24.67 83.78,24.67 79.03,29.42 71.34,29.42 70.7,28.78 67.52,28.78 67.09,28.35 65.56,28.35 v1(65.31,28.1)
UART8_TX: length 12.7
  TOP w0.127: J44.11 110.14,6.64 109.29,7.49 R365.8 109.6,8.22 109.97,8.22 110.31,8.56 110.31,10.03 110.55,10.27 111.49,10.27 111.96,10.74 112.34,10.74 112.46,10.85 112.46,10.88 112.5,10.93 112.5,11.54 112.32,11.72 U42.10
UART8_TX_M0: length 128.3
  TOP w0.127: R365.1 109.29,9.5 v1(109.36,9.57) ; v1(65.31,28.86) 65.01,29.17 65.01,39.66 64.48,40.18 64.48,41.08 63.68,41.89 63.68,45.55 62.03,47.19 62.03,48.74 60.33,50.45 60.33,51.03 60.33,51.24 57.23,54.35 49.13,54.35 48.5,54.98 42.39,54.98 40.48,56.89 39.89,56.89 39.22,57.55 39.22,58.37 38.87,58.72 M1.86
  BOTTOM w0.127: v1(109.36,9.57) 110.14,8.8 116.45,8.8 117.32,9.67 118.82,9.67 119.33,10.18 119.33,11.3 117.02,13.61 116,13.61 114.17,15.43 114.17,15.85 113.14,16.89 110.56,16.89 110.41,17.03 103.68,17.03 102.6,18.11 92.22,18.11 87.51,22.82 86.77,22.82 84.67,24.92 83.89,24.92 79.13,29.68 71.23,29.68 70.59,29.04 67.42,29.04 66.99,28.61 65.56,28.61 v1(65.31,28.86)
UART9_RX_M1: length 101.5
  TOP w0.127: v1(107.61,9.57) 107.69,9.49 R365.4 ; M1.77 47.87,61.99 49.84,60.02 52.03,60.02 52.41,59.64 56.52,59.64 63.6,52.56 63.6,50.59 64.6,49.59 64.6,48.35 66.31,46.64 66.31,43.25 67.05,42.51 67.05,41.48 67.48,41.04 67.48,30.63 68.02,30.09 68.02,27.29 66.58,25.85 66.58,24.07 66.58,22.37 v1(66.37,22.16)
  BOTTOM w0.127: v1(107.61,9.57) 104.53,9.57 102.58,11.52 98.48,11.52 97.67,12.33 89.66,12.33 84.98,17.01 84.05,17.01 77.64,23.42 72.74,23.42 72.4,23.76 71.36,23.76 70.74,23.13 70.18,23.13 69.26,22.21 66.43,22.21 66.38,22.16 v1(66.37,22.16)
UART9_TX_M1: length 103.6
  TOP w0.127: R365.3 108.24,9.73 v1(108.26,9.76) ; M1.78 46.87,62.01 47.28,61.6 47.9,61.6 49.73,59.77 51.93,59.77 52.31,59.38 56.41,59.38 63.34,52.45 63.34,50.49 64.35,49.49 64.35,48.24 66.06,46.53 66.06,43.15 66.79,42.41 66.79,41.37 67.23,40.94 67.23,30.5 67.77,29.96 67.77,27.4 66.33,25.96 66.33,24.18 66.33,24.18 66.33,23.05 v1(65.69,22.41)
  BOTTOM w0.127: v1(108.26,9.76) 107.93,10.09 104.57,10.09 102.89,11.78 98.59,11.78 97.78,12.59 89.77,12.59 85.08,17.27 84.16,17.27 77.75,23.68 72.84,23.68 72.51,24.01 71.26,24.01 70.64,23.39 70.08,23.39 69.43,22.74 66.02,22.74 v1(65.69,22.41)
USB20_HOST1_DM: length 38
  TOP w0.114: U7.30 107.9,44.1 107.74,43.94 104.49,43.94 102.65,45.78 102.65,46.79 102.09,47.35 102.09,48.87 101.32,49.64 100.77,49.64 v1(100.49,49.92) ; M1.22 82.87,40.19 83.25,40.57 83.62,40.57 83.96,40.91 89.22,40.91 92.99,44.68 92.99,47.64 95.21,49.86 96.01,49.86 96.35,50.2 96.35,50.4 v1(96.65,50.71)
  BOTTOM w0.114: v1(100.49,49.92) 100.21,49.64 98.52,49.64 98.35,49.81 96.66,49.81 96.41,50.06 96.41,50.46 v1(96.65,50.71)
USB20_HOST1_DP: length 38
  TOP w0.114: U7.31 107.83,43.6 107.73,43.7 104.39,43.7 102.41,45.68 102.41,46.69 101.85,47.25 101.85,48.77 101.22,49.4 100.79,49.4 100.65,49.26 100.64,49.26 v1(100.49,49.11) ; v1(95.85,50.71) 96,50.56 96,50.55 96.11,50.44 96.11,50.3 95.91,50.1 95.11,50.1 92.75,47.74 92.75,44.78 89.12,41.15 83.86,41.15 83.52,40.81 83.25,40.81 82.87,41.19 M1.23
  BOTTOM w0.114: v1(100.49,49.11) 100.3,49.31 100.29,49.31 100.2,49.4 98.42,49.4 98.25,49.57 96.56,49.57 96.17,49.96 96.17,50.37 95.85,50.69 v1(95.85,50.71)
USB30_OTG0_DM: length 60.5
  TOP w0.114: R247.1 75.94,76.45 75.94,75.98 81.1,70.83 82.12,70.83 82.91,70.04 83.21,70.04 83.61,69.63 83.61,69.4 v1(83.33,69.12) ; M1.18 82.79,36.19 82.95,36.34 83.81,36.34 85.75,38.27 87,38.27 87.75,39.02 87.75,39.28 v1(88.03,39.56)
  BOTTOM w0.114: v1(83.33,69.12) 83.61,69.4 83.61,69.75 83.85,70 84.63,70 86.46,68.17 89.25,68.17 91.33,66.09 91.33,50.59 89.68,48.93 88.68,48.93 87.6,47.85 87.6,47.32 87.94,46.97 88.77,46.97 90.01,45.73 90.01,42.56 87.75,40.3 87.75,39.84 v1(88.03,39.56)
USB30_OTG0_DP: length 60.4
  TOP w0.114: v1(84.13,69.12) 83.85,69.4 83.85,69.73 83.31,70.28 83.01,70.28 82.22,71.07 81.2,71.07 81.08,71.18 81.08,71.36 80.84,71.61 80.66,71.61 80.42,71.85 80.42,72.03 80.18,72.27 80,72.27 77.51,74.75 77.51,74.93 77.27,75.18 77.09,75.18 76.85,75.42 76.85,75.6 76.61,75.84 76.43,75.84 76.18,76.08 76.18,76.59 76.27,76.67 R248.1 ; v1(87.22,39.56) 87.5,39.28 87.5,39.12 86.9,38.51 85.65,38.51 83.71,36.58 83.15,36.58 82.99,36.73 82.99,37.02 82.83,37.19 M1.19
  BOTTOM w0.114: v1(84.13,69.12) 83.85,69.4 83.85,69.65 83.95,69.76 84.53,69.76 86.36,67.93 89.15,67.93 91.09,65.99 91.09,50.69 89.58,49.17 88.58,49.17 87.36,47.95 87.36,47.22 87.84,46.73 88.67,46.73 89.77,45.63 89.77,42.66 87.5,40.4 87.5,39.84 v1(87.22,39.56)
USB30_OTG0_ID: length 38.9
  TOP w0.127: v1(92.79,62.64) 92.6,62.83 92.11,62.83 91.98,62.7 Q6.3 ; v1(98.42,50.72) 98.42,50.42 97.1,49.11 95.63,49.11 93.74,47.22 93.74,44.28 89.62,40.15 86.55,40.15 86,39.61 84.56,39.61 83.14,38.19 M1.20
  BOTTOM w0.127: v1(92.79,62.64) 93.59,61.84 93.59,57.73 94.64,56.69 94.64,54.84 98.42,51.06 v1(98.42,50.72)
USB30_OTG0_SSRXN/PCIE20_RXDN: length 5.7
  TOP w0.114: M1.27 82.57,45.19 83,44.76 83.79,44.76 84.44,44.11 86.02,44.11 86.27,44.36 v1(86.34,44.36) R406.1
  BOTTOM w0.114: R406.1 v1(86.34,44.36)
USB30_OTG0_SSRXP/PCIE20_RXDP: length 5.7
  TOP w0.114: M1.26 82.79,44.19 83.13,44.52 83.69,44.52 84.34,43.87 86.02,43.87 86.27,43.62 v1(86.34,43.62) 86.37,43.59 R405.1
  BOTTOM w0.114: v1(86.34,43.62) 86.37,43.59 R405.1
USB30_OTG0_SSTXN/PCIE20_TXDN: length 5.6
  TOP w0.114: M1.25 82.53,43.19 82.72,43 83.46,43 84.08,42.38 86.07,42.38 v1(86.39,42.7) C354.2
  BOTTOM w0.114: C354.2 v1(86.39,42.7)
USB30_OTG0_SSTXP/PCIE20_TXDP: length 5.8
  TOP w0.114: C353.2 v1(86.39,41.82) 86.07,42.14 83.98,42.14 83.36,42.76 83.12,42.76 82.94,42.58 82.94,42.43 82.7,42.19 M1.24
  BOTTOM w0.114: C353.2 v1(86.39,41.82)
USB30_OTG0_VBUSDET: length 44.8
  TOP w0.127: R353.2 R445.1 R253.2 C347.2 91.02,65.57 91.02,62.2 91.49,61.74 92.64,61.74 v1(92.78,61.88) ; v1(97.74,50.71) 97.74,50.11 97,49.36 95.52,49.36 93.49,47.33 93.49,44.38 89.52,40.41 86.45,40.41 85.9,39.86 84.46,39.86 83.78,39.19 M1.21
  BOTTOM w0.127: v1(92.78,61.88) 93.34,61.33 93.34,57.63 94.38,56.58 94.38,54.74 97.74,51.38 v1(97.74,50.71)
USB_HOST2_PWREN_H: length 1.6
  TOP w0.127: U6.4 105.72,69.76 R1168.1
USB_HOST3_PWREN_H: length 42.5
  TOP w0.127: v1(94.06,61.08) 94.71,61.08 96.4,62.77 112.17,62.77 112.98,63.58 122.14,63.58 v1(122.23,63.48) ; v1(124.35,59.98) 125.19,59.13 U4.4 125.19,58.7 R450.1 ; R430.1 94.27,57.44 v1(94.52,57.69)
  BOTTOM w0.127: v1(122.23,63.48) 123.4,62.31 123.4,60.93 v1(124.35,59.98) ; v1(94.52,57.69) 94.06,58.16 v1(94.06,61.08)
USB_HOST4_PWREN_H: length 128.8
  TOP w0.127: v1(112.2,78.23) 114.2,78.23 114.83,77.6 114.83,75.2 113.41,73.78 113.41,64.83 v1(114.21,64.04) ; U5.4 125.19,47.03 R451.1 v1(124.7,47.02) ; v1(67.22,68.61) 67.85,67.98 68.31,67.98 70.26,69.93 73.45,69.93 74.78,71.26 74.78,73.84 74.89,73.95 v1(74.89,74.18) ; v1(54.53,72.69) 52.99,72.69 52.31,72.01 50.86,72.01 50.52,72.36 50.52,72.61 49.67,73.45 48.59,73.45 47.82,72.68 47.82,71.61 46.35,70.14 45.36,70.14 43.4,68.17 R1082.1
  BOTTOM w0.127: v1(112.2,78.23) 111.82,78.6 100.94,78.6 99.81,77.47 97.37,77.47 93.86,73.96 81.44,73.96 79.85,72.36 76.04,72.36 74.89,73.52 v1(74.89,74.18) ; v1(114.21,64.04) 114.76,64.6 115.71,64.6 116.05,64.26 116.05,63.26 119.08,60.23 123.35,60.23 124.7,58.88 v1(124.7,47.02) ; v1(54.53,72.69) 56.52,70.71 61.03,70.71 61.96,69.78 63.36,69.78 64.06,69.08 66.75,69.08 v1(67.22,68.61)
USB_OTG: length 18.8
  TOP w0.127: U29.1 94.07,70.58 93,69.5 93,68.67 R445.2
  TOP w0.508: 96.43,76.99 v1(96.04,77.38) 95.69,77.02 v1(95.59,77.02) 95.59,74.76 95.09,74.26 C261.1 95.09,70.69 U29.1
  BOTTOM w0.127: v1(95.59,77.02) 95.59,77.45 92.74,80.3
  BOTTOM w1.016: 92.74,80.3 J42.1
USB_OTG_DET_GPIO0_C0_D: length 72
  TOP w0.127: v1(67.45,43.72) 67.45,43.23 68.36,42.32 68.36,40.52 67.74,39.9 67.74,30.75 68.27,30.22 68.27,27.19 66.84,25.75 66.84,23.97 66.83,23.97 66.83,20.2 66.35,19.72 66.35,18.88 66.87,18.36 M1.158 ; v1(87.15,58.33) 87.15,59.6 90.77,63.21 90.77,69.31 91.14,69.68 91.87,69.68 R353.1
  BOTTOM w0.127: v1(67.45,43.72) 67.7,43.97 79.13,43.97 82.33,47.17 82.33,49.73 85.73,53.13 85.73,57.41 86.65,58.33 v1(87.15,58.33)
USB_OTG_DM: length 16.6
  TOP w0.114: R247.2 76.05,77.9 76.05,79.18 D37.2 75.93,79.76 76.05,79.88 76.05,80.33 76.3,80.59 81.77,80.59 82.69,81.5 86.82,81.5 J42.2
USB_OTG_DP: length 16.6
  TOP w0.114: R248.2 76.29,77.9 76.29,79.18 D38.2 76.4,79.76 76.29,79.88 76.29,80.23 76.4,80.35 81.87,80.35 82.79,81.26 86.72,81.26 87.15,80.83 87.15,80.42 87.03,80.3 J42.3
USB_OTG_PWREN: length 15.4
  TOP w0.127: v1(94.27,62.52) 95.08,62.52 97.54,64.97 97.54,66.82 97.75,67.04 98.73,67.04 R352.1 ; R429.1 94.27,58.45 v1(94.52,58.71)
  BOTTOM w0.127: v1(94.52,58.71) 94.56,58.75 94.56,62.22 v1(94.27,62.52)
USB_OTG_PWREN_H: length 11.6
  TOP w0.127: R456.1 92.9,65.06 94.17,63.79 95.99,63.79 97.28,65.08 97.28,66.93 97.65,67.29 98.08,67.29 R352.2 98.74,68.36 98.42,68.68 U29.4
USB_OTG_SSRXN: length 17.1
  TOP w0.114: J42.5 83.79,78.8 83.91,78.68 83.91,78.05 84.42,77.53 84.42,76.59 83.91,76.07 83.91,74.6 82.65,73.34 82.65,72.65 D42.2 82.65,71.69 82.65,71.39 83.27,70.77 83.52,70.77 85.31,68.98 85.31,68.17 86.87,66.61 86.87,66.19 R410.2
USB_OTG_SSRXP: length 17.1
  TOP w0.114: R409.2 87.11,66.19 87.11,66.71 85.55,68.27 85.55,69.08 83.62,71.01 83.37,71.01 82.89,71.49 82.89,71.69 D41.2 82.89,72.65 82.89,73.24 84.15,74.5 84.15,75.97 84.67,76.49 84.67,77.63 84.15,78.15 84.15,78.68 84.26,78.8 J42.6
USB_OTG_SSTXN: length 16.3
  TOP w0.114: C346.1 89.16,66.19 89.16,69.58 91.29,71.72 91.29,72.02 91.14,72.17 D40.2 91.29,72.65 91.29,73.12 89.91,74.5 89.91,76.06 89.43,76.54 89.43,77.65 89.91,78.13 89.91,78.68 89.79,78.8 J42.8
USB_OTG_SSTXP: length 16.3
  TOP w0.114: C345.1 89.4,66.19 89.4,69.48 91.53,71.62 91.53,72.05 91.65,72.17 D39.2 91.53,72.65 91.53,73.22 90.15,74.6 90.15,76.16 89.67,76.64 89.67,77.55 90.15,78.03 90.15,78.68 90.26,78.8 J42.9
USB_PCIE_RXN: length 27.2
  TOP w0.114: v1(86.58,64.48) 86.58,64.93 R410.1
  BOTTOM w0.114: R410.1 86.55,64.52 v1(86.58,64.48) 86.86,64.2 86.86,63.85 87.11,63.61 87.11,63.43 87.35,63.19 87.53,63.19 87.77,62.94 87.77,62.76 88.01,62.52 88.19,62.52 88.44,62.28 88.44,62.1 88.68,61.86 88.86,61.86 89.48,61.23 89.48,60.78 89.38,60.67 89.38,60.28 89.48,60.18 89.48,51.16 89.05,50.73 87.96,50.73 85.88,48.65 85.88,46.38 87.06,45.21 87.92,45.21 88.26,44.87 88.26,44.24 88.18,44.15 88.06,44.15 R1204.2
USB_PCIE_RXP: length 27.2
  TOP w0.114: R409.1 87.39,64.91 v1(87.39,64.48)
  BOTTOM w0.114: R1203.2 88.05,43.91 88.28,43.91 88.5,44.14 88.5,44.97 88.02,45.45 87.15,45.45 86.13,46.48 86.13,48.55 88.06,50.49 89.15,50.49 89.72,51.06 89.72,61.33 87.1,63.95 87.1,64.2 v1(87.39,64.48) 87.43,64.53 R409.1
USB_PCIE_TXN: length 28.9
  TOP w0.114: v1(88.88,64.47) 88.88,64.92 C346.2
  BOTTOM w0.114: C346.2 88.88,64.92 v1(88.88,64.47) 89.12,64.22 89.12,63.42 90.36,62.19 90.36,61.8 90.23,61.67 90.23,61.33 90.36,61.2 90.36,60.86 90.23,60.73 90.23,60.39 90.36,60.26 90.36,56.06 90.23,55.93 90.23,55.59 90.36,55.46 90.36,55.12 90.23,54.99 90.23,54.65 90.36,54.52 90.36,50.99 89.3,49.93 88.3,49.93 86.62,48.25 86.62,46.73 87.39,45.97 88.27,45.97 89.03,45.21 89.03,42.97 88.45,42.38 88.06,42.38 R1205.2
USB_PCIE_TXP: length 28.9
  TOP w0.114: C345.2 89.68,64.92 v1(89.68,64.47)
  BOTTOM w0.114: C345.2 89.72,64.63 89.72,64.51 v1(89.68,64.47) 89.37,64.15 89.37,63.52 90.6,62.29 90.6,50.89 89.4,49.69 88.4,49.69 86.86,48.15 86.86,46.83 87.49,46.21 88.37,46.21 89.28,45.31 89.28,42.87 88.55,42.14 88.06,42.14 R1206.2
USIM_CLK: length 2.7
  TOP w0.127: R55.1 116.75,55.99 116.78,56.02 J10.12
VOLN: length 15.4
  TOP w0.508: v1(77.64,2.6) 77.64,3.39 79.09,4.83 79.48,4.83 80.62,5.98 C216.1 80.38,6.88 80.38,7.64 L25.2
  BOTTOM w0.508: J35.1 70.66,1.91 76.56,1.91 77.24,2.6 v1(77.64,2.6)
VOLP: length 16.3
  TOP w0.508: L26.2 82.78,7.01 C217.1 82.78,6.2 82.46,5.87 81.42,5.87 79.69,4.15 79.43,4.15 78.46,3.17 78.46,2.08 77.93,1.56 73.02,1.56 J35.2
VORN: length 7.8
  TOP w0.508: J35.3 74.66,3.88 76.33,3.88 78.46,6 C220.1 78.46,7.66 L27.2
VORP: length 9.5
  TOP w0.508: L28.2 76.3,7.4 C221.1 76.3,6.47 76.87,5.9 v1(76.87,5.55) ; J35.4 76.25,2.9 78.9,5.55 v1(79.19,5.55)
  BOTTOM w0.508: v1(79.19,5.55) v1(76.87,5.55)
WIFI1T1R_CLK: length 3
  TOP w0.127: U18.17 C170.2 R227.2
WIFI1T1R_XTAL_IN: length 7.6
  TOP w0.127: U18.10 123.95,27 124.87,27.92 124.87,28.83 125.06,29.01 125.35,29.01 C167.2 125.95,29.29 128.38,29.29 128.57,29.1 XT5.3
WIFI1T1R_XTAL_OUT: length 5.6
  TOP w0.127: XT5.1 126.77,29.79 126.6,29.62 125.87,29.62 C171.2 124.54,29.02 124.54,28.2 124.24,27.9 U18.11
WIFI_REG_ON_H: length 26.4
  TOP w0.127: v1(116.19,14.67) 115.63,14.67 R246.1 ; v1(124.87,31.79) 124.68,31.98 R229.2 R238.1
  BOTTOM w0.127: v1(124.87,31.79) 124.87,31.44 125.28,31.03 125.28,30.64 125.04,30.41 125.04,26.15 125.46,25.73 125.46,24.82 125,24.35 122.77,24.35 118.78,20.35 118.78,16.8 117.76,15.78 117.3,15.78 v1(116.19,14.67)
WIFI_REG_ON_H_GPIO0_A0_D: length 77.7
  TOP w0.127: v1(93.87,8.54) 95.65,10.32 98.3,10.32 98.82,10.84 101.43,10.84 101.65,11.06 v1(102.14,11.06) ; v1(124.81,30.84) 124.57,31.08 R229.1 ; M1.172 80.87,16.4 v1(83.75,13.52)
  BOTTOM w0.127: v1(124.81,30.84) 124.79,30.81 124.79,26.05 125.21,25.63 125.21,24.92 124.89,24.6 122.65,24.6 118.52,20.48 118.52,16.92 117.63,16.03 116.9,16.03 115.72,14.86 115.72,14.29 116.14,13.86 117.12,13.86 119.58,11.4 119.58,10.08 118.92,9.42 117.43,9.42 116.55,8.54 104.76,8.54 102.25,11.06 v1(102.14,11.06) ; v1(93.87,8.54) 93.63,8.3 87.29,8.3 84.39,11.19 84.39,12.88 v1(83.75,13.52)
WIFIBT_32KIN_1T1R: length 3
  TOP w0.127: U18.24 111.1,27 111.06,26.96 C180.2 R243.2
N19354508: length 3.3
  TOP w0.508: U13.4 52.25,8.67 C1048.1 R136.1 R137.2
N19356461: length 2.4
  TOP w0.254: U11.4 9.41,10.87 9.29,10.76 R133.2 8.8,10.35 8.98,10.17 R132.1
N19357233: length 3
  TOP w0.254: R134.1 R135.2 29.22,18.83 29.44,18.61 U12.4
N19411583: length 20.8
  TOP w0.127: R157.1 55.66,68.43 55.66,75.22 59.72,79.28 59.72,82.51 J21.14
N19487510: length 3.5
  TOP w0.254: R443.2 R80.1 10.52,39.47 10.57,39.53 C84.1 11.27,39.85 11.02,40.1 Q3.1
N19487520: length 2.9
  TOP w0.254: R443.1 8.99,38.57 8.54,39.02 8.54,39.75 8.8,40 9.01,40 9.3,40.29 Q4.3
N20425490: length 17
  TOP w0.127: J21.11 69.65,85.24 66.43,82.02 66.43,78.87 72.25,73.06 R150.1
N69227918: length 4.1
  TOP w0.254: R10.2 R8.1 C31.1 24.67,35.02 U3.5
N69724413: length 3.2
  TOP w0.254: U3.1 26.9,35.02 26.45,34.58 C37.2 R9.2
N69763264: length 6.1
  TOP w0.254: C1049.1 86.44,35.72 82.91,32.19 M1.14
N69763270: length 6.1
  TOP w0.254: C1050.1 86.24,34.7 82.72,31.19 M1.13
N69764395: length 2.8
  TOP w0.127: J10.10 117.58,55.97 117.76,55.79 R54.1
N69764397: length 2.8
  TOP w0.127: R56.1 115.73,55.71 115.98,55.96 J10.14
N69764433: length 1.4
  TOP w0.508: LED2.A 91.18,59.69 R452.1
N69764492: length 2.9
  TOP w0.127: U9.1 91.55,51.13 91.8,50.88 92.36,50.88 92.72,50.53 92.86,50.53 R441.2
N69764501: length 4.4
  TOP w0.254: R442.2 R60.1 C79.1 90.46,50.58 89.12,51.91 U9.5
N69764582: length 2.8
  TOP w0.254: R52.1 118.38,55.35 J10.8
N69765778: length 1.2
  TOP w0.254: U4.3 125.19,62.76 R31.1
N69765789: length 1.2
  TOP w0.254: U5.3 125.19,50.92 R34.1
N69765908: length 2
  TOP w0.254: U7.48 115.69,38.58 115.73,38.54 R439.1
N69765931: length 3
  TOP w0.254: U7.36 107.85,41.1 107.31,40.56 107.31,40.29 R438.1
N69765961: length 2.2
  TOP w0.254: U7.5 118.38,43.1 118.65,42.83 R435.2
N69765963: length 2.2
  TOP w0.254: U7.7 118.53,44.1 118.78,43.85 R436.2
N69774873: length 2
  TOP w0.254: U18.29 110.97,22.5 110.95,22.51 R244.2
N69774879: length 3.4
  TOP w0.127: U18.34 113.39,16.79 R245.2 R246.2
N69774884: length 3
  TOP w0.508: R225.1 C168.2 U18.2
N69774885: length 2.7
  TOP w0.508: R225.2 C169.2 J24.2
N69774891:
  vias: v1(110.52,28.73) v1(111.28,28.73) v1(115.65,34.02) v1(116.36,33.61)
N69774994: length 2
  TOP w0.127: R238.2 122.33,30.28 122.39,30.23 U18.12
N69783431: length 2.4
  TOP w0.254: J28.1 128.2,40.31 127.3,39.41 D43.C
N69783435: length 2.9
  TOP w0.254: J28.2 127.99,41.56 R464.2
N69783454: length 1.5
  TOP w0.254: D43.A 125.95,39.85 R463.2
N69784782: length 4.2
  TOP w0.127: XT6.1 59.6,11.11 59.85,10.85 60.83,10.85 C189.2 61.66,11.68 U20.1
N69784786: length 4.4
  TOP w0.127: U20.2 62.14,11.03 C191.2 60.86,10.52 59.85,10.52 59.6,10.27 XT6.2
N69784848: length 51.9
  TOP w0.508: v1(25.09,20.18) 25.09,23.92 J47.1 ; v1(58.91,16.18) 59.68,15.4 61.37,15.4 63.53,13.24 D49.A ; v1(26.47,15.99) 25.89,16.57 25.89,19.62 26.5,20.22 v1(26.5,20.61)
  BOTTOM w0.508: v1(58.91,16.18) 58.29,16.18 57.65,15.54 53.11,15.54 52.55,16.1 43.12,16.1 41.16,14.13 37.87,14.13 37.07,14.94 34.89,14.94 33.85,15.99 v1(26.47,15.99) ; v1(26.5,20.61) 25.52,20.61 v1(25.09,20.18)
N69791555: length 2.8
  TOP w0.254: R434.2 119.06,39.99 117.95,41.1 U7.1
N69811295: length 1.5
  BOTTOM w0.254: R84.1 7.14,54.64 7.21,54.58 U10.3
N69814289: length 2.9
  TOP w0.381: R19.2 77.76,87.61 LED1.1
N69814308: length 2.4
  TOP w0.305: Q1.3 74.2,86.77 73.87,87.1 LED1.2
N69814328: length 2.8
  TOP w0.305: Q1.1 73.7,84.88 74.07,85.25 74.71,85.25 75.16,85.7 R21.2
N69841804: length 2.6
  TOP w0.508: F3.2 13.48,69.83 ; F3.2 12.61,68.95 ; F3.2 11.73,69.83
N69861791: length 5.6
  TOP w0.254: v1(5.07,45.88) 5.64,45.31 5.64,43.38 5.82,43.2 5.86,43.2 5.95,43.11 J13.1
  BOTTOM w0.381: R62.2 C82.2 5.07,45.87 v1(5.07,45.88)
N69863607: length 2.4
  BOTTOM w0.254: R465.2 127.41,83.03 C281.2 127.67,83.03 R388.1
N69863700: length 2.7
  TOP w0.254: R387.1 115.42,70.26 C280.2 116.05,70.2 116.3,69.95 R466.2
N69865878: length 7.9
  TOP w0.127: J37.5 123.12,77.25 D67.1 123.12,73.87 123.15,73.84 C223.2 R314.1 R455.2
N69867903: length 15.5
  TOP w0.508: L26.1 83.28,8.35 83.59,8.66 92.12,8.66 94.8,11.34 U25.1
N69867905: length 19.9
  TOP w0.508: L25.1 80.47,9.29 91.75,9.29 93.38,10.92 93.38,12.99 94.27,13.88 U25.3
N69867925: length 19.1
  TOP w0.508: U25.14 92.11,13.88 92.62,13.37 92.62,11.08 91.46,9.93 79.74,9.93 78.93,9.11 L27.1
N69867927: length 15.3
  TOP w0.508: U25.16 90.46,11.34 89.68,10.56 79.48,10.56 78.79,9.87 77.37,9.87 L28.1
N69867929: length 1.1
  TOP w0.254: R303.1 93.98,22.51 C215.2
N69867931: length 5.1
  TOP w0.254: U25.7 95.89,18.96 95.18,19.67 95.18,22.21 R303.2
